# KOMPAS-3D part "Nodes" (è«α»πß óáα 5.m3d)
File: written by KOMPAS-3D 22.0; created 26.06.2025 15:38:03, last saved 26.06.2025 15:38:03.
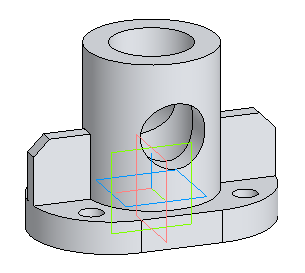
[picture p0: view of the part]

Document properties: Автор: Helen; Полное имя файла: D:\MY\WORK\MPEI\ППЭ_2025-2026\Варианты\Вап 5 СБ\Корпус вар 5.m3d

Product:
- Part/product: Nodes

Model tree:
1. Операция без истории:1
